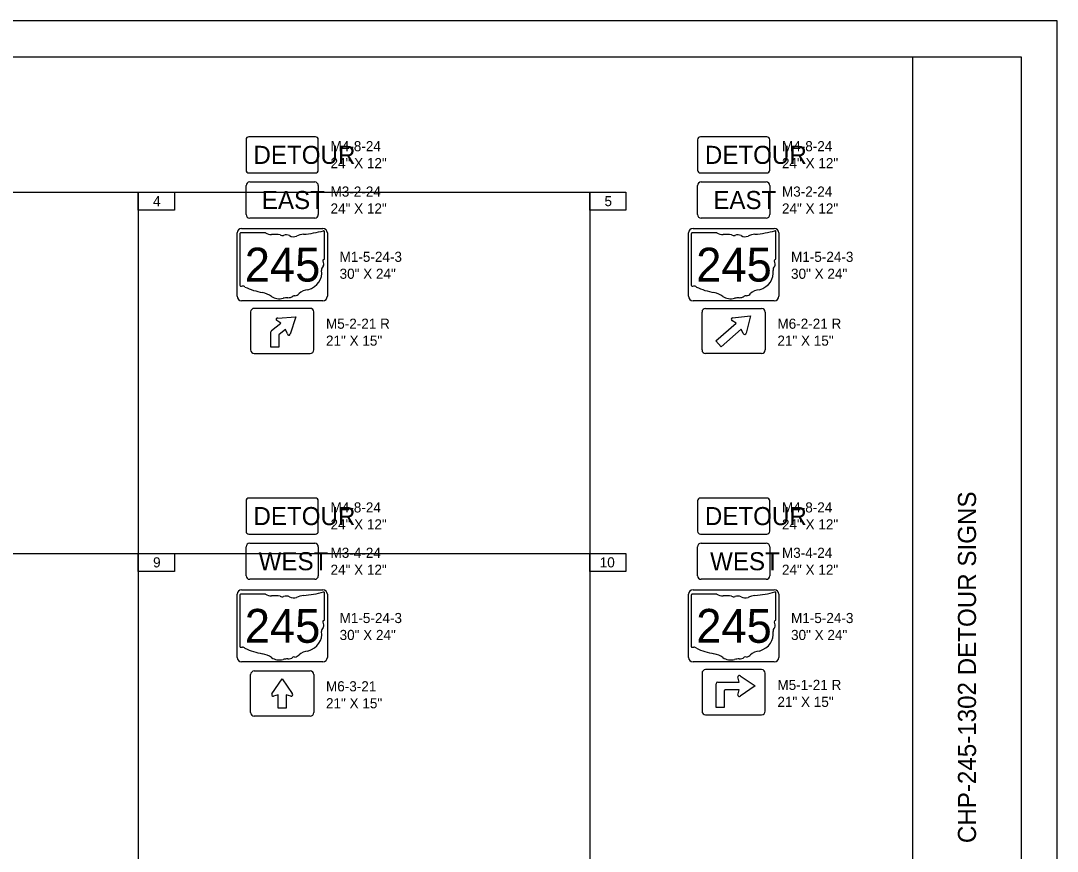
# Model space of a CAD drawing. Extents: x 0 to 718, y 0 to 440.
# Drawn here: x 393 to 680, y 210.1 to 440 of the extents above; entities that cross this region are included whole.
import ezdxf

# ---------------------------------------------------------------- set-up
doc = ezdxf.new("R2010")
doc.units = 0
for name, color, linetype in [('SC_Scratch1', 7, 'Continuous'), ('SH_Border', 7, 'Continuous'), ('SH_Cut_Line', 7, 'Continuous'), ('SH_Data', 7, 'Continuous'), ('SH_Text', 7, 'Continuous'), ('SN_P_Signs', 7, 'Continuous'), ('SN_P_Text', 7, 'Continuous')]:
    doc.layers.add(name, color=color, linetype=linetype)

msp = doc.modelspace()

# ---------------------------------------------------------------- linework, layer by layer
at = {"layer": 'SC_Scratch1'}
for p, q in [((375.54, 392.53), (550.54, 392.53)), ((425.54, 392.53), (425.54, 292.53)), ((550.54, 392.53), (550.54, 292.53)), ((375.54, 292.53), (550.54, 292.53)), ((425.54, 292.53), (425.54, 192.53)), ((550.54, 292.53), (550.54, 192.53))]:
    msp.add_line(p, q, dxfattribs=at)
at = {"layer": 'SH_Border'}
msp.add_line((640, 10), (640, 430), dxfattribs=at)
msp.add_lwpolyline([(30, 430), (670, 430), (670, 10), (30, 10)], close=True, dxfattribs=at)
at = {"layer": 'SH_Cut_Line'}
msp.add_lwpolyline([(0, 0), (680, 0), (680, 440), (0, 440)], close=True, dxfattribs=at)
at = {"layer": 'SH_Text'}
for points in [[(425.54, 392.53), (435.54, 392.53), (435.54, 387.53), (425.54, 387.53)], [(550.54, 392.53), (560.54, 392.53), (560.54, 387.53), (550.54, 387.53)], [(425.54, 292.53), (435.54, 292.53), (435.54, 287.53), (425.54, 287.53)], [(550.54, 292.53), (560.54, 292.53), (560.54, 287.53), (550.54, 287.53)]]:
    msp.add_lwpolyline(points, close=True, dxfattribs=at)
at = {"layer": 'SN_P_Signs'}
for p, q in [((455.39, 386.37), (455.39, 394.37)), ((456.39, 395.37), (474.39, 395.37)), ((475.39, 394.37), (475.39, 386.37)), ((580.39, 386.37), (580.39, 394.37)), ((581.39, 395.37), (599.39, 395.37)), ((600.39, 394.37), (600.39, 386.37)), ((474.39, 385.37), (456.39, 385.37)), ((599.39, 385.37), (581.39, 385.37)), ((453.67, 381.02), (453.67, 366.79)), ((460.76, 381.26), (453.9, 381.26)), ((477.11, 374.17), (477.11, 381.61)), ((578.67, 381.02), (578.67, 366.79)), ((585.76, 381.26), (578.9, 381.26)), ((602.11, 374.17), (602.11, 381.61)), ((477.1, 374.17), (477.11, 374.17)), ((602.1, 374.17), (602.11, 374.17)), ((456.64, 359.37), (456.64, 348.87)), ((473.14, 360.37), (457.64, 360.37)), ((474.14, 348.87), (474.14, 359.37)), ((581.64, 348.86), (581.64, 359.36)), ((582.64, 360.36), (598.14, 360.36)), ((599.14, 359.36), (599.14, 348.86)), ((462.45, 354.26), (464.97, 356.24)), ((464.97, 356.24), (463.86, 356.99)), ((464.13, 357.7), (469.14, 358.01)), ((464.13, 357.7), (464.13, 357.7)), ((469.14, 358.01), (467.63, 353.22)), ((585.45, 351.34), (591.07, 356.26)), ((591.07, 356.26), (589.92, 356.97)), ((590.09, 357.74), (595.08, 358.33)), ((590.09, 357.74), (590.09, 357.74)), ((595.08, 358.33), (593.85, 353.54)), ((462.26, 349.59), (462.26, 353.89)), ((466.32, 354.51), (464.57, 353.14)), ((466.81, 353.35), (466.32, 354.51)), ((592.51, 354.62), (586.89, 349.69)), ((593.05, 353.39), (592.51, 354.62)), ((464.45, 352.9), (464.45, 349.59)), ((586.89, 349.69), (585.45, 351.34)), ((457.64, 347.87), (473.14, 347.87)), ((464.45, 349.59), (462.26, 349.59)), ((598.14, 347.86), (582.64, 347.86)), ((455.39, 286.37), (455.39, 294.37)), ((456.39, 295.37), (474.39, 295.37)), ((475.39, 294.37), (475.39, 286.37)), ((580.39, 286.37), (580.39, 294.37)), ((581.39, 295.37), (599.39, 295.37)), ((600.39, 294.37), (600.39, 286.37)), ((474.39, 285.37), (456.39, 285.37)), ((599.39, 285.37), (581.39, 285.37)), ((477.11, 274.17), (477.11, 281.61)), ((602.11, 274.17), (602.11, 281.61)), ((453.67, 281.02), (453.67, 266.79)), ((460.76, 281.26), (453.9, 281.26)), ((578.67, 281.02), (578.67, 266.79)), ((585.76, 281.26), (578.9, 281.26)), ((477.1, 274.17), (477.11, 274.17)), ((602.1, 274.17), (602.11, 274.17)), ((456.64, 248.49), (456.64, 258.99)), ((457.64, 259.99), (473.14, 259.99)), ((474.14, 258.99), (474.14, 248.49)), ((581.64, 259.37), (581.64, 248.87)), ((598.14, 260.37), (582.64, 260.37)), ((591.95, 256.93), (591.53, 258.33)), ((592.24, 258.63), (596.32, 255.83)), ((599.14, 248.87), (599.14, 259.37)), ((462.54, 253.66), (465.39, 257.8)), ((465.39, 257.8), (468.18, 253.72)), ((585.54, 249.9), (585.54, 256.46)), ((586.01, 256.93), (591.95, 256.93)), ((586.01, 256.93), (586.01, 256.93)), ((596.32, 255.83), (592.24, 253.04)), ((464.29, 253.42), (463.01, 253.03)), ((464.29, 249.67), (464.29, 253.42)), ((467.76, 253.03), (466.48, 253.42)), ((466.48, 253.42), (466.48, 249.67)), ((587.73, 254.43), (587.73, 249.9)), ((591.95, 254.74), (588.04, 254.74)), ((591.53, 253.33), (591.95, 254.74)), ((587.73, 249.9), (585.54, 249.9)), ((473.14, 247.49), (457.64, 247.49)), ((466.48, 249.67), (464.29, 249.67)), ((582.64, 247.87), (598.14, 247.87))]:
    msp.add_line(p, q, dxfattribs=at)
for points in [[(474.59, 407.87), (456.19, 407.87)], [(599.59, 407.87), (581.19, 407.87)], [(455.39, 407.07), (455.39, 398.67)], [(475.39, 398.67), (475.39, 407.07)], [(580.39, 407.07), (580.39, 398.67)], [(600.39, 398.67), (600.39, 407.07)], [(456.19, 397.87), (474.59, 397.87)], [(581.19, 397.87), (599.59, 397.87)], [(454.14, 382.49), (476.64, 382.49)], [(579.14, 382.49), (601.64, 382.49)], [(452.89, 363.74), (452.89, 381.24)], [(477.89, 381.24), (477.89, 363.74)], [(577.89, 363.74), (577.89, 381.24)], [(602.89, 381.24), (602.89, 363.74)], [(476.64, 362.49), (454.14, 362.49)], [(601.64, 362.49), (579.14, 362.49)], [(474.59, 307.87), (456.19, 307.87)], [(599.59, 307.87), (581.19, 307.87)], [(455.39, 307.07), (455.39, 298.67)], [(475.39, 298.67), (475.39, 307.07)], [(580.39, 307.07), (580.39, 298.67)], [(600.39, 298.67), (600.39, 307.07)], [(456.19, 297.87), (474.59, 297.87)], [(581.19, 297.87), (599.59, 297.87)], [(454.14, 282.49), (476.64, 282.49)], [(579.14, 282.49), (601.64, 282.49)], [(452.89, 263.74), (452.89, 281.24)], [(477.89, 281.24), (477.89, 263.74)], [(577.89, 263.74), (577.89, 281.24)], [(602.89, 281.24), (602.89, 263.74)], [(476.64, 262.49), (454.14, 262.49)], [(601.64, 262.49), (579.14, 262.49)]]:
    msp.add_lwpolyline(points, dxfattribs=at)
for centre, radius, start, end in [((456.19, 407.07), 0.8, 90, 180), ((474.59, 407.07), 0.8, 0, 90), ((581.19, 407.07), 0.8, 90, 180), ((599.59, 407.07), 0.8, 0, 90), ((456.19, 398.67), 0.8, 180, 270), ((474.59, 398.67), 0.8, 270, 0), ((581.19, 398.67), 0.8, 180, 270), ((599.59, 398.67), 0.8, 270, 0), ((456.39, 394.36), 1, 90, 180), ((474.39, 394.36), 1, 0, 90), ((581.39, 394.36), 1, 90, 180), ((599.39, 394.36), 1, 0, 90), ((456.39, 386.36), 1, 180, 270), ((474.39, 386.36), 1, 270, 0), ((581.39, 386.36), 1, 180, 270), ((599.39, 386.36), 1, 270, 0), ((454.14, 381.24), 1.25, 90, 180), ((476.64, 381.24), 1.25, 0, 90), ((579.14, 381.24), 1.25, 90, 180), ((601.64, 381.24), 1.25, 0, 90), ((454.14, 363.74), 1.25, 180, 270), ((476.64, 363.74), 1.25, 270, 0), ((579.14, 363.74), 1.25, 180, 270), ((601.64, 363.74), 1.25, 270, 0), ((457.64, 359.37), 1, 90, 180), ((473.14, 359.37), 1, 0, 90), ((582.64, 359.36), 1, 90, 180), ((598.14, 359.36), 1, 0, 90), ((464.15, 357.29), 0.417, 93.5999, 225.0001), ((590.14, 357.32), 0.417, 96.6699, 238.4633), ((462.73, 353.89), 0.468, 127.7857, 180), ((464.76, 352.9), 0.312, 127.3494, 180), ((467.23, 353.35), 0.417, 180.0509, 342.5804), ((593.43, 353.56), 0.417, 204.0541, 356.2683), ((457.64, 348.87), 1, 180, 270), ((473.14, 348.87), 1, 270, 360), ((582.64, 348.86), 1, 180, 270), ((598.14, 348.86), 1, 270, 0), ((456.19, 307.07), 0.8, 90, 180), ((474.59, 307.07), 0.8, 0, 90), ((581.19, 307.07), 0.8, 90, 180), ((599.59, 307.07), 0.8, 0, 90), ((456.19, 298.67), 0.8, 180, 270), ((474.59, 298.67), 0.8, 270, 0), ((581.19, 298.67), 0.8, 180, 270), ((599.59, 298.67), 0.8, 270, 0), ((456.39, 294.36), 1, 90, 180), ((474.39, 294.36), 1, 0, 90), ((581.39, 294.36), 1, 90, 180), ((599.39, 294.36), 1, 0, 90), ((456.39, 286.36), 1, 180, 270), ((474.39, 286.36), 1, 270, 0), ((581.39, 286.36), 1, 180, 270), ((599.39, 286.36), 1, 270, 0), ((454.14, 281.24), 1.25, 90, 180), ((476.64, 281.24), 1.25, 0, 90), ((579.14, 281.24), 1.25, 90, 180), ((601.64, 281.24), 1.25, 0, 90), ((454.14, 263.74), 1.25, 180, 270), ((476.64, 263.74), 1.25, 270, 0), ((579.14, 263.74), 1.25, 180, 270), ((601.64, 263.74), 1.25, 270, 0), ((457.64, 258.99), 1, 90, 180), ((473.14, 258.99), 1, 0, 90), ((582.64, 259.36), 1, 90, 180), ((591.95, 258.33), 0.417, 45.0001, 179.9983), ((598.14, 259.36), 1, 0, 90), ((586.01, 256.46), 0.469, 90, 180), ((462.89, 253.43), 0.417, 145.4112, 287.2046), ((467.89, 253.43), 0.417, 252.7954, 45.0096), ((588.04, 254.43), 0.312, 90, 180), ((591.95, 253.33), 0.417, 179.9983, 314.9999), ((457.64, 248.49), 1, 180, 270), ((473.14, 248.49), 1, 270, 0), ((582.64, 248.86), 1, 180, 270), ((598.14, 248.86), 1, 270, 0)]:
    msp.add_arc(centre, radius, start, end, dxfattribs=at)
for centre, major_axis, start_param, end_param in [((468.76, 400.66), (24.85, 0), 4.814394, 5.042369), ((476.85, 381.64), (0.261, 0), 6.141152, 7.989035), ((593.76, 400.66), (24.85, 0), 4.814394, 5.042369), ((601.85, 381.64), (0.261, 0), 6.141152, 7.989035), ((453.94, 381.05), (0.272, 0), 1.712693, 3.28349), ((462.4, 382.91), (2.63, 0), 4.042523, 4.731795), ((463.27, 373.27), (9.45, 0), 1.404758, 1.657858), ((465.42, 381.12), (0.76, 0), 3.836095, 5.185415), ((466.53, 379.48), (1.58, 0), 0.950623, 2.079405), ((468.57, 381.73), (1.9, 0), 4.081561, 5.145723), ((471.93, 376.91), (5, 0), 1.699011, 2.107814), ((578.94, 381.05), (0.272, 0), 1.712693, 3.28349), ((587.4, 382.91), (2.63, 0), 4.042523, 4.731795), ((588.27, 373.27), (9.45, 0), 1.404758, 1.657858), ((590.42, 381.12), (0.76, 0), 3.836095, 5.185415), ((591.53, 379.48), (1.58, 0), 0.950623, 2.079405), ((593.57, 381.73), (1.9, 0), 4.081561, 5.145723), ((596.93, 376.91), (5, 0), 1.699011, 2.107814), ((477.05, 373.62), (0.404, 0), 1.883978, 3.671073), ((474.48, 372.68), (2.42, 0), 5.934695, 6.695948), ((476.83, 374.14), (0.279, 0), 5.05454, 6.418171), ((602.05, 373.62), (0.404, 0), 1.883978, 3.671073), ((599.48, 372.68), (2.42, 0), 5.934695, 6.695948), ((601.83, 374.14), (0.279, 0), 5.05454, 6.418171), ((470.15, 370.11), (6.22, 0), 5.101752, 6.440018), ((478.04, 371.05), (1.76, 0), 2.387724, 3.262537), ((595.15, 370.11), (6.22, 0), 5.101752, 6.440018), ((603.04, 371.05), (1.76, 0), 2.387724, 3.262537), ((453.94, 366.75), (0.274, 0), 3.00124, 4.508301), ((453.98, 368.21), (2.09, 0), 4.665946, 4.897461), ((454.41, 365.96), (0.754, 0), 0.519207, 1.627899), ((463.93, 378.75), (17.95, 0), 4.195997, 4.488961), ((458.57, 360.39), (5.62, 0), 0.823519, 1.323587), ((472.77, 362.79), (3.4, 0), 1.647645, 2.488434), ((578.94, 366.75), (0.274, 0), 3.00124, 4.508301), ((578.98, 368.21), (2.09, 0), 4.665946, 4.897461), ((579.41, 365.96), (0.754, 0), 0.519207, 1.627899), ((588.93, 378.75), (17.95, 0), 4.195997, 4.488961), ((583.57, 360.39), (5.62, 0), 0.823519, 1.323587), ((597.77, 362.79), (3.4, 0), 1.647645, 2.488434), ((464.65, 365.89), (3.56, 0), 4.026481, 4.996735), ((466.71, 360.97), (2.93, 0), 1.495662, 1.94098), ((466.97, 364.83), (1.9, 0), 4.691044, 5.507374), ((468.69, 363.45), (0.535, 0), 1.147584, 2.315152), ((468.46, 365.41), (2.01, 0), 4.937069, 5.64225), ((589.65, 365.89), (3.56, 0), 4.026481, 4.996735), ((591.71, 360.97), (2.93, 0), 1.495662, 1.94098), ((591.97, 364.83), (1.9, 0), 4.691044, 5.507374), ((593.69, 363.45), (0.535, 0), 1.147584, 2.315152), ((593.46, 365.41), (2.01, 0), 4.937069, 5.64225), ((468.76, 300.66), (24.85, 0), 4.814394, 5.042369), ((476.85, 281.64), (0.261, 0), 6.141152, 7.989035), ((593.76, 300.66), (24.85, 0), 4.814394, 5.042369), ((601.85, 281.64), (0.261, 0), 6.141152, 7.989035), ((453.94, 281.05), (0.272, 0), 1.712693, 3.28349), ((462.4, 282.91), (2.63, 0), 4.042523, 4.731795), ((463.27, 273.27), (9.45, 0), 1.404758, 1.657858), ((465.42, 281.12), (0.76, 0), 3.836095, 5.185415), ((466.53, 279.48), (1.58, 0), 0.950623, 2.079405), ((468.57, 281.73), (1.9, 0), 4.081561, 5.145723), ((471.93, 276.91), (5, 0), 1.699011, 2.107814), ((578.94, 281.05), (0.272, 0), 1.712693, 3.28349), ((587.4, 282.91), (2.63, 0), 4.042523, 4.731795), ((588.27, 273.27), (9.45, 0), 1.404758, 1.657858), ((590.42, 281.12), (0.76, 0), 3.836095, 5.185415), ((591.53, 279.48), (1.58, 0), 0.950623, 2.079405), ((593.57, 281.73), (1.9, 0), 4.081561, 5.145723), ((596.93, 276.91), (5, 0), 1.699011, 2.107814), ((477.05, 273.62), (0.404, 0), 1.883978, 3.671073), ((474.48, 272.68), (2.42, 0), 5.934695, 6.695948), ((476.83, 274.14), (0.279, 0), 5.05454, 6.418171), ((602.05, 273.62), (0.404, 0), 1.883978, 3.671073), ((599.48, 272.68), (2.42, 0), 5.934695, 6.695948), ((601.83, 274.14), (0.279, 0), 5.05454, 6.418171), ((470.15, 270.11), (6.22, 0), 5.101752, 6.440018), ((478.04, 271.05), (1.76, 0), 2.387724, 3.262537), ((595.15, 270.11), (6.22, 0), 5.101752, 6.440018), ((603.04, 271.05), (1.76, 0), 2.387724, 3.262537), ((453.94, 266.75), (0.274, 0), 3.00124, 4.508301), ((453.98, 268.21), (2.09, 0), 4.665946, 4.897461), ((454.41, 265.96), (0.754, 0), 0.519207, 1.627899), ((463.93, 278.75), (17.95, 0), 4.195997, 4.488961), ((458.57, 260.39), (5.62, 0), 0.823519, 1.323587), ((468.46, 265.41), (2.01, 0), 4.937069, 5.64225), ((472.77, 262.79), (3.4, 0), 1.647645, 2.488434), ((578.94, 266.75), (0.274, 0), 3.00124, 4.508301), ((578.98, 268.21), (2.09, 0), 4.665946, 4.897461), ((579.41, 265.96), (0.754, 0), 0.519207, 1.627899), ((588.93, 278.75), (17.95, 0), 4.195997, 4.488961), ((583.57, 260.39), (5.62, 0), 0.823519, 1.323587), ((593.46, 265.41), (2.01, 0), 4.937069, 5.64225), ((597.77, 262.79), (3.4, 0), 1.647645, 2.488434), ((464.65, 265.89), (3.56, 0), 4.026481, 4.996735), ((466.71, 260.97), (2.93, 0), 1.495662, 1.94098), ((466.97, 264.83), (1.9, 0), 4.691044, 5.507374), ((468.69, 263.45), (0.535, 0), 1.147584, 2.315152), ((589.65, 265.89), (3.56, 0), 4.026481, 4.996735), ((591.71, 260.97), (2.93, 0), 1.495662, 1.94098), ((591.97, 264.83), (1.9, 0), 4.691044, 5.507374), ((593.69, 263.45), (0.535, 0), 1.147584, 2.315152)]:
    msp.add_ellipse(centre, major_axis=major_axis, ratio=0.8, start_param=start_param, end_param=end_param, dxfattribs=at)

# ---------------------------------------------------------------- texts
at = {"layer": 'SH_Data'}
msp.add_text('CHP-245-1302 DETOUR SIGNS', height=5, rotation=90, dxfattribs=at).set_placement((657.5, 212.33))
at = {"layer": 'SH_Text'}
for s, p in [('4', (429.63, 388.66)), ('5', (554.63, 388.66)), ('9', (429.63, 288.66)), ('10', (553.31, 288.66))]:
    msp.add_text(s, height=2.8, dxfattribs=at).set_placement(p)
at = {"layer": 'SN_P_Signs'}
for s, height, p in [('DETOUR', 5, (457.42, 400.37)), ('DETOUR', 5, (582.42, 400.37)), ('EAST', 5, (459.75, 387.87)), ('EAST', 5, (584.75, 387.87)), ('245', 9.375, (455.03, 367.79)), ('245', 9.375, (580.03, 367.79)), ('DETOUR', 5, (457.42, 300.37)), ('DETOUR', 5, (582.42, 300.37)), ('WEST', 5, (458.86, 287.87)), ('WEST', 5, (583.86, 287.87)), ('245', 9.375, (455.03, 267.79)), ('245', 9.375, (580.03, 267.79))]:
    msp.add_text(s, height=height, dxfattribs=at).set_placement(p)
at = {"layer": 'SN_P_Text'}
for s, p in [('M4-8-24', (478.77, 403.87)), ('M4-8-24', (603.77, 403.87)), ('24" X 12"', (478.77, 399.18)), ('24" X 12"', (603.77, 399.18)), ('M3-2-24', (478.77, 391.31)), ('M3-2-24', (603.77, 391.31)), ('24" X 12"', (478.77, 386.62)), ('24" X 12"', (603.77, 386.62)), ('M1-5-24-3', (481.28, 373.25)), ('M1-5-24-3', (606.28, 373.25)), ('30" X 24"', (481.28, 368.56)), ('30" X 24"', (606.28, 368.56)), ('M5-2-21 R', (477.51, 354.73)), ('M6-2-21 R', (602.51, 354.73)), ('21" X 15"', (477.51, 350.04)), ('21" X 15"', (602.51, 350.04)), ('M4-8-24', (478.77, 303.87)), ('M4-8-24', (603.77, 303.87)), ('24" X 12"', (478.77, 299.18)), ('24" X 12"', (603.77, 299.18)), ('M3-4-24', (478.77, 291.31)), ('M3-4-24', (603.77, 291.31)), ('24" X 12"', (478.77, 286.62)), ('24" X 12"', (603.77, 286.62)), ('M1-5-24-3', (481.28, 273.25)), ('M1-5-24-3', (606.28, 273.25)), ('30" X 24"', (481.28, 268.56)), ('30" X 24"', (606.28, 268.56)), ('M6-3-21', (477.51, 254.35)), ('M5-1-21 R', (602.51, 254.73)), ('21" X 15"', (602.51, 250.04)), ('21" X 15"', (477.51, 249.66))]:
    msp.add_text(s, height=2.8, dxfattribs=at).set_placement(p)

doc.saveas('drawing.dxf')
